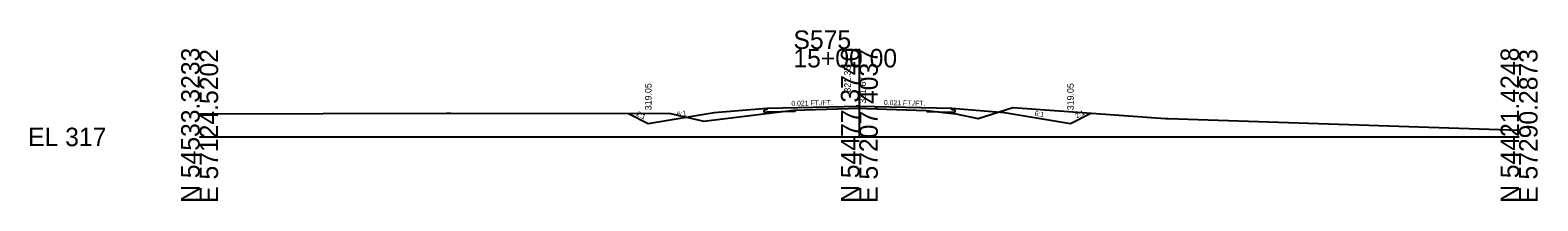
# Model space of a CAD drawing. Extents: x 10119 to 10347, y 94341 to 98867.
# Drawn here: x 10118.6 to 10347.2, y 98841.1 to 98867 of the extents above; entities that cross this region are included whole.
import ezdxf

# ---------------------------------------------------------------- set-up
doc = ezdxf.new("R2010")
doc.units = 0
for name, color, linetype in [('Level 10', 7, 'Continuous'), ('Level 11', 7, 'Continuous'), ('Level 12', 7, 'Continuous'), ('Level 32', 7, 'Continuous'), ('Level 33', 7, 'Continuous'), ('Level 59', 7, 'Continuous'), ('Level 6', 7, 'Continuous'), ('Level 60', 7, 'Continuous'), ('Level 63', 7, 'Continuous'), ('Level 7', 7, 'Continuous')]:
    doc.layers.add(name, color=color, linetype=linetype)

msp = doc.modelspace()

# ---------------------------------------------------------------- linework, layer by layer
at = {"layer": 'Level 11'}
for p, q in [((10230.31, 98854.9), (10229.81, 98854.89)), ((10229.81, 98854.89), (10229.81, 98854.55)), ((10229.81, 98854.55), (10230.31, 98854.56)), ((10230.31, 98855.19), (10230.31, 98854.9)), ((10258.31, 98854.9), (10258.31, 98855.19)), ((10258.81, 98854.89), (10258.31, 98854.9)), ((10258.31, 98854.56), (10258.81, 98854.55)), ((10258.81, 98854.55), (10258.81, 98854.89))]:
    msp.add_line(p, q, dxfattribs=at)
at = {"layer": 'Level 12'}
for p, q in [((10234.57, 98854.65), (10230.31, 98854.56)), ((10234.57, 98854.88), (10234.57, 98854.65)), ((10254.53, 98854.79), (10254.53, 98854.64)), ((10254.53, 98854.64), (10258.31, 98854.56))]:
    msp.add_line(p, q, dxfattribs=at)
at = {"layer": 'Level 59'}
for p, q in [((10230.31, 98855.19), (10244.31, 98855.48)), ((10244.31, 98855.48), (10258.31, 98855.19))]:
    msp.add_line(p, q, dxfattribs=at)
at = {"layer": 'Level 6'}
for p, q in [((10222.31, 98854.52), (10230.31, 98855.19)), ((10258.31, 98855.19), (10266.31, 98854.52))]:
    msp.add_line(p, q, dxfattribs=at)
at = {"layer": 'Level 60'}
for p, q in [((10220.73, 98853.2), (10234.31, 98854.87)), ((10234.31, 98854.87), (10244.31, 98855.16)), ((10244.31, 98855.16), (10245.45, 98855.12)), ((10245.45, 98855.12), (10254.44, 98854.79)), ((10254.44, 98854.79), (10258.93, 98854.33)), ((10262.32, 98853.6), (10267.58, 98855.26)), ((10267.58, 98855.26), (10290.73, 98853.59)), ((10144.31, 98854.3), (10181.72, 98854.39)), ((10181.72, 98854.39), (10182.39, 98854.41)), ((10182.39, 98854.41), (10215.68, 98854.34)), ((10215.68, 98854.34), (10220.73, 98853.2)), ((10258.93, 98854.33), (10262.32, 98853.6)), ((10290.73, 98853.59), (10291.1, 98853.58)), ((10291.1, 98853.58), (10344.31, 98851.81))]:
    msp.add_line(p, q, dxfattribs=at)
at = {"layer": 'Level 63'}
for p, q in [((10244.31, 98850.81), (10244.31, 98864.15)), ((10144.31, 98850.81), (10244.31, 98850.81)), ((10244.31, 98850.81), (10344.31, 98850.81))]:
    msp.add_line(p, q, dxfattribs=at)
at = {"layer": 'Level 7'}
for p, q in [((10212.31, 98852.86), (10222.31, 98854.52)), ((10266.31, 98854.52), (10276.31, 98852.86)), ((10209.32, 98854.35), (10212.31, 98852.86)), ((10276.31, 98852.86), (10279.42, 98854.41))]:
    msp.add_line(p, q, dxfattribs=at)

# ---------------------------------------------------------------- texts
at = {"layer": 'Level 10'}
msp.add_text('321.35', height=1, rotation=90, dxfattribs=at).set_placement((10243, 98857.52))
at = {"layer": 'Level 32'}
for s, rotation, p in [('2:1', 333.435, (10210.42, 98854.08)), ('6:1', 9.4623, (10216.75, 98853.85)), ('0.021 FT./FT.', 1.1916, (10234.02, 98855.52)), ('0.021 FT./FT.', 358.8084, (10248.03, 98855.65)), ('6:1', 350.5377, (10270.83, 98854.02)), ('2:1', 26.5651, (10277.25, 98853.6))]:
    msp.add_text(s, height=0.75, rotation=rotation, dxfattribs=at).set_placement(p)
at = {"layer": 'Level 33'}
for p in [(10212.81, 98854.86), (10276.81, 98854.86)]:
    msp.add_text('319.05', height=1, rotation=90, dxfattribs=at).set_placement(p)
at = {"layer": 'Level 59'}
msp.add_text(' 321.67', height=1, rotation=90, dxfattribs=at).set_placement((10245.31, 98855.48))
at = {"layer": 'Level 63'}
for s, p in [('S575', (10234.32, 98864.15)), ('15+00.00', (10234.31, 98861.35)), ('EL 317', (10118.31, 98849.41))]:
    msp.add_text(s, height=2.8, dxfattribs=at).set_placement(p)
for s, p in [('N 54533.3233', (10144.31, 98840.81)), ('E 57124.5202', (10147.11, 98840.81)), ('N 54477.3740', (10244.31, 98840.81)), ('E 57207.4037', (10247.11, 98840.81)), ('N 54421.4248', (10344.31, 98840.81)), ('E 57290.2873', (10347.11, 98840.81))]:
    msp.add_text(s, height=2.8, rotation=90, dxfattribs=at).set_placement(p)

doc.saveas('drawing.dxf')
